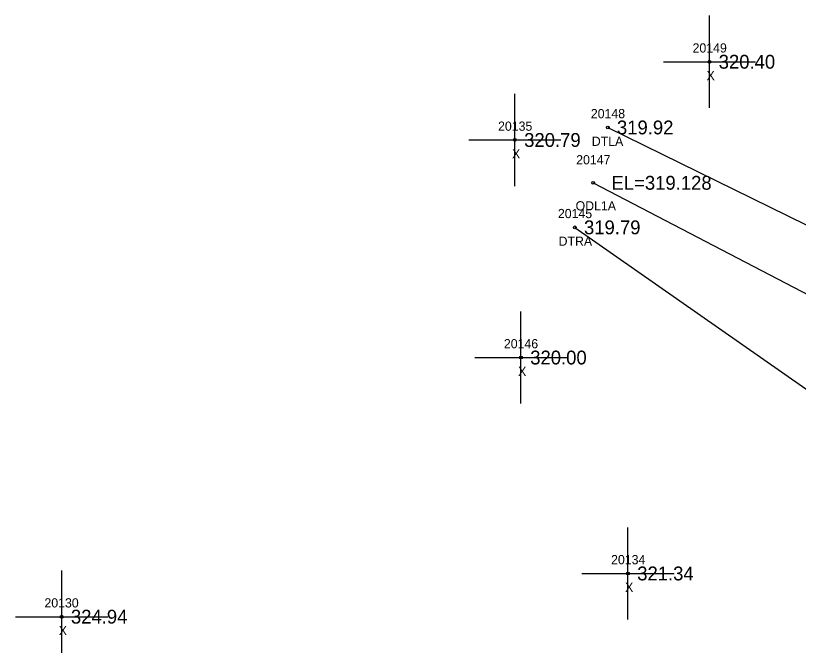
# Model space of a CAD drawing. Extents: x 2231109 to 2232328, y 1035718 to 1036919.
# Drawn here: x 2231405.9 to 2231490.9, y 1036447.8 to 1036516.1 of the extents above; entities that cross this region are included whole.
import ezdxf

# ---------------------------------------------------------------- set-up
doc = ezdxf.new("R2010")
doc.units = 0
for name, color, linetype in [('RD_EX_H2O', 7, 'Continuous'), ('RD_EX_H2O_txCode', 7, 'Continuous'), ('RD_EX_Misc', 7, 'Continuous'), ('RD_EX_Misc_txCode', 7, 'Continuous'), ('RD_EX_TX_H2O_ELEV', 7, 'Continuous'), ('RD_EX_TX_Misc_ELEV', 7, 'Continuous'), ('RD_SMD_Locator', 7, 'Continuous')]:
    doc.layers.add(name, color=color, linetype=linetype)

msp = doc.modelspace()

# ---------------------------------------------------------------- linework, layer by layer
at = {"layer": 'RD_EX_H2O'}
for points in [[(2231470.157, 1036503.998), (2231509.272, 1036484.816), (2231533.671, 1036469.129), (2231543.463, 1036469.508)], [(2231468.565, 1036497.993), (2231506.861, 1036478.057), (2231532.329, 1036461.936), (2231550.778, 1036464.109)], [(2231466.578, 1036493.157), (2231498.133, 1036471.126), (2231516.436, 1036459.048), (2231550.294, 1036452.225)]]:
    msp.add_lwpolyline(points, dxfattribs=at)
at = {"layer": 'RD_EX_Misc'}
for p, q in [((2231481.205, 1036506.127), (2231481.205, 1036516.127)), ((2231476.205, 1036511.127), (2231486.205, 1036511.127)), ((2231460.078, 1036497.639), (2231460.078, 1036507.639)), ((2231455.078, 1036502.639), (2231465.078, 1036502.639)), ((2231460.736, 1036474.033), (2231460.736, 1036484.033)), ((2231455.736, 1036479.033), (2231465.736, 1036479.033)), ((2231472.356, 1036450.605), (2231472.356, 1036460.605)), ((2231410.854, 1036445.914), (2231410.854, 1036455.914)), ((2231467.356, 1036455.605), (2231477.356, 1036455.605)), ((2231405.854, 1036450.914), (2231415.854, 1036450.914))]:
    msp.add_line(p, q, dxfattribs=at)
at = {"layer": 'RD_SMD_Locator'}
for centre in [(2231481.205, 1036511.127), (2231470.157, 1036503.998), (2231460.078, 1036502.639), (2231468.565, 1036497.993), (2231466.578, 1036493.157), (2231460.736, 1036479.033), (2231472.356, 1036455.605), (2231410.854, 1036450.914)]:
    msp.add_circle(centre, 0.15, dxfattribs=at)

# ---------------------------------------------------------------- texts
at = {"layer": 'RD_EX_H2O_txCode'}
for s, p in [('20148', (2231468.322, 1036504.998)), ('DTLA', (2231468.424, 1036501.998)), ('20147', (2231466.73, 1036499.993)), ('20145', (2231464.744, 1036494.157)), ('ODL1A', (2231466.667, 1036494.993)), ('DTRA', (2231464.822, 1036491.157))]:
    msp.add_text(s, height=1, dxfattribs=at).set_placement(p)
at = {"layer": 'RD_EX_Misc_txCode'}
for s, p in [('20149', (2231479.37, 1036512.127)), ('X', (2231480.89, 1036509.127)), ('20135', (2231458.244, 1036503.639)), ('X', (2231459.763, 1036500.639)), ('20146', (2231458.878, 1036480.033)), ('X', (2231460.421, 1036477.033)), ('20134', (2231470.522, 1036456.605)), ('X', (2231472.041, 1036453.605)), ('20130', (2231408.98, 1036451.914)), ('X', (2231410.539, 1036448.914))]:
    msp.add_text(s, height=1, dxfattribs=at).set_placement(p)
at = {"layer": 'RD_EX_TX_H2O_ELEV'}
for s, p in [('319.92', (2231471.157, 1036503.248)), ('EL=319.128', (2231470.565, 1036497.243)), ('319.79', (2231467.578, 1036492.407))]:
    msp.add_text(s, height=1.5, dxfattribs=at).set_placement(p)
at = {"layer": 'RD_EX_TX_Misc_ELEV'}
for s, p in [('320.40', (2231482.205, 1036510.377)), ('320.79', (2231461.078, 1036501.889)), ('320.00', (2231461.736, 1036478.283)), ('321.34', (2231473.356, 1036454.855)), ('324.94', (2231411.854, 1036450.164))]:
    msp.add_text(s, height=1.5, dxfattribs=at).set_placement(p)

doc.saveas('drawing.dxf')
